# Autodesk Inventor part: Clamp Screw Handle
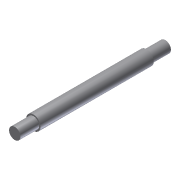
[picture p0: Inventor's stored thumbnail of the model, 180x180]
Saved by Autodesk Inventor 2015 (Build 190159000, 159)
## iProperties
Shininess: 77.0
Length Units: 11269
Angle Units: 11279
Time Units: 11290
Mass Units: 11283
Length Display Precision: 3
Angle Display Precision: 2
Compacted: True
Created: 2002-02
Part Number: Clamp Screw Handle
Document SubType Name: Modeling
Designer: ***
Density: 1 g/cm^3
Material: Generic
Appearance: Default
Density: 0.0
Volumn: 0.0
Area: 0.0
PropertySet Name: Model Information
Control State: 0
Master: False
Checked Out: False
Author: ***
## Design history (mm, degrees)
sketch "Sketch1"
  geometry: L1 (0, 105)-(4, 105); L2 (4, 105)-(4, 92); L3 (4, 92)-(5, 92); L4 (5, 92)-(5, 13); L5 (5, 13)-(4, 13); L6 (4, 13)-(4, 0); L7 (4, 0)-(0, 0); L8 (0, 0)-(0, 105)
  constraints: 16 end point, 5 parallel, 2 equal length, 1 collinear, 1 horizontal, 1 perpendicular
  dimensions: "d0" = 10 diameter of L4 L8; "d1" = 8 diameter of L2 L8; "d2" = 13 distance of L1.end L2.end; "d3" = 79 distance of L3.end L4.end
revolve "Revolution1" sketch "Sketch1" stored, may be unused: angle "d4" = 90 deg
body "Solid1"
